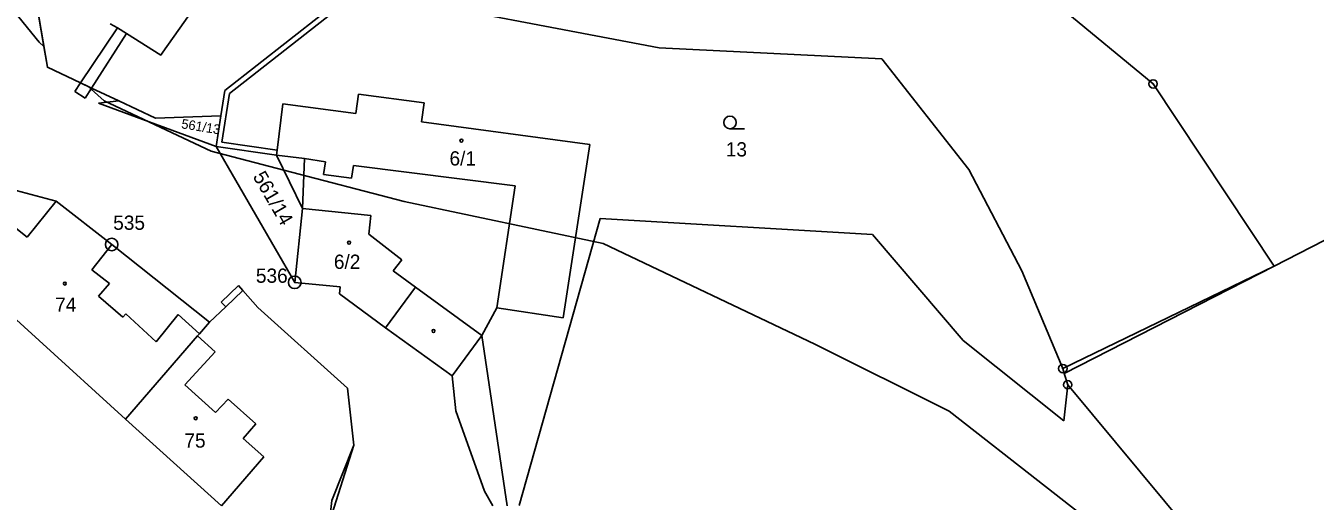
# Model space of a CAD drawing. Extents: x -725765 to -723182, y -1052705 to -1049154.
# Drawn here: x -724740.7 to -724587, y -1050771.8 to -1050715 of the extents above; entities that cross this region are included whole.
import ezdxf

# ---------------------------------------------------------------- set-up
doc = ezdxf.new("R2010")
doc.units = 0
for name, color, linetype in [('Vrstva 1', 7, 'Continuous'), ('Vrstva 17', 7, 'Continuous'), ('Vrstva 18', 7, 'Continuous'), ('Vrstva 19', 7, 'Continuous'), ('Vrstva 25', 7, 'Continuous'), ('Vrstva 4', 7, 'Continuous'), ('Vrstva 52', 7, 'Continuous')]:
    doc.layers.add(name, color=color, linetype=linetype)

msp = doc.modelspace()

# ---------------------------------------------------------------- linework, layer by layer
at = {"layer": 'Vrstva 1'}
for points in [[(-724741.74, -1050698.99), (-724738.17, -1050719.97)], [(-724724.39, -1050718.17), (-724717.58, -1050708.46)], [(-724716.99, -1050722.76), (-724701.57, -1050710.63)], [(-724700.87, -1050710.84), (-724665.21, -1050717.66)], [(-724617.37, -1050712.82), (-724606.3, -1050721.96)], [(-724730.67, -1050714.79), (-724729.82, -1050715.26)], [(-724729.82, -1050715.26), (-724728.73, -1050715.96)], [(-724728.73, -1050715.96), (-724724.64, -1050718.52)], [(-724665.21, -1050717.66), (-724638.64, -1050718.98)], [(-724724.64, -1050718.52), (-724724.39, -1050718.17)], [(-724638.64, -1050718.98), (-724628.28, -1050732.18)], [(-724738.17, -1050719.97), (-724734.22, -1050721.83)], [(-724734.22, -1050721.83), (-724732.9, -1050722.45)], [(-724732.9, -1050722.45), (-724729.65, -1050723.98)], [(-724606.3, -1050721.96), (-724591.87, -1050743.69)], [(-724732.06, -1050724.25), (-724729.65, -1050723.98)], [(-724732.06, -1050724.25), (-724718.05, -1050729.41)], [(-724729.65, -1050723.98), (-724725.26, -1050726.05)], [(-724717.47, -1050725.76), (-724716.99, -1050722.76)], [(-724701.4, -1050725.49), (-724701.07, -1050723.18)], [(-724701.07, -1050723.18), (-724693.23, -1050724.2)], [(-724693.53, -1050726.5), (-724693.23, -1050724.2)], [(-724725.26, -1050726.05), (-724717.47, -1050725.76)], [(-724718.05, -1050729.41), (-724717.47, -1050725.76)], [(-724710.77, -1050729.85), (-724710.07, -1050724.33)], [(-724710.07, -1050724.33), (-724701.4, -1050725.49)], [(-724693.53, -1050726.5), (-724673.48, -1050729.18)], [(-724718.05, -1050729.41), (-724708.67, -1050745.64)], [(-724718.05, -1050729.41), (-724710.85, -1050730.45)], [(-724710.85, -1050730.45), (-724710.77, -1050729.85)], [(-724676.64, -1050749.89), (-724673.48, -1050729.18)], [(-724591.87, -1050743.69), (-724565.12, -1050730)], [(-724710.85, -1050730.45), (-724707.75, -1050736.81)], [(-724747.3, -1050733.24), (-724737.14, -1050735.96)], [(-724628.28, -1050732.18), (-724621.93, -1050744.27)], [(-724737.14, -1050735.96), (-724730.5, -1050741.12)], [(-724708.67, -1050745.64), (-724707.75, -1050736.81)], [(-724707.75, -1050736.81), (-724699.6, -1050737.65)], [(-724699.84, -1050739.89), (-724699.6, -1050737.65)], [(-724681.91, -1050772.28), (-724672.23, -1050738.03)], [(-724672.23, -1050738.03), (-724639.76, -1050739.93)], [(-724730.5, -1050741.12), (-724718.82, -1050750.37)], [(-724699.84, -1050739.89), (-724695.9, -1050742.96)], [(-724639.76, -1050739.93), (-724628.95, -1050752.57)], [(-724749.48, -1050743.18), (-724728.86, -1050761.96)], [(-724696.91, -1050744.25), (-724695.9, -1050742.96)], [(-724696.91, -1050744.25), (-724694.25, -1050746.21)], [(-724621.93, -1050744.27), (-724617.06, -1050755.93)], [(-724617.06, -1050755.93), (-724591.87, -1050743.69)], [(-724708.67, -1050745.64), (-724703.25, -1050746.18)], [(-724716.88, -1050748.54), (-724714.85, -1050746.62)], [(-724714.85, -1050746.62), (-724713.07, -1050748.63)], [(-724703.33, -1050747.02), (-724703.25, -1050746.18)], [(-724703.33, -1050747.02), (-724697.83, -1050751.07)], [(-724697.83, -1050751.07), (-724694.25, -1050746.21)], [(-724718.82, -1050750.37), (-724716.88, -1050748.54)], [(-724713.07, -1050748.63), (-724702.37, -1050758.27)], [(-724686.37, -1050751.98), (-724684.58, -1050748.68)], [(-724684.58, -1050748.68), (-724676.64, -1050749.89)], [(-724720.03, -1050751.77), (-724718.82, -1050750.37)], [(-724720.26, -1050752.02), (-724720.03, -1050751.77)], [(-724697.83, -1050751.07), (-724689.9, -1050756.78)], [(-724728.86, -1050761.96), (-724720.26, -1050752.02)], [(-724689.9, -1050756.78), (-724686.37, -1050751.98)], [(-724686.37, -1050751.98), (-724683.34, -1050772.29)], [(-724628.95, -1050752.57), (-724616.96, -1050762.18)], [(-724617.06, -1050755.93), (-724616.89, -1050756.5)], [(-724616.89, -1050756.5), (-724616.48, -1050757.85)], [(-724616.96, -1050762.18), (-724616.48, -1050757.85)], [(-724616.48, -1050757.85), (-724599.21, -1050778.62)], [(-724702.37, -1050758.27), (-724701.62, -1050765.05)], [(-724728.86, -1050761.96), (-724717.41, -1050772.31)], [(-724704.54, -1050774.22), (-724701.62, -1050765.05)]]:
    msp.add_lwpolyline(points, dxfattribs=at)
at = {"layer": 'Vrstva 25'}
msp.add_lwpolyline([(-724656.76, -1050727.31), (-724655.01, -1050727.31)], dxfattribs=at)
for centre, radius in [((-724606.3, -1050721.96), 0.5), ((-724606.3, -1050721.96), 0.032), ((-724656.76, -1050726.56), 0.75), ((-724688.79, -1050728.73), 0.175), ((-724730.5, -1050741.12), 0.75), ((-724730.5, -1050741.12), 0.032), ((-724702.19, -1050740.9), 0.175), ((-724736.09, -1050745.78), 0.175), ((-724708.67, -1050745.64), 0.75), ((-724708.67, -1050745.64), 0.032), ((-724692.12, -1050751.44), 0.175), ((-724617.06, -1050755.93), 0.5), ((-724617.06, -1050755.93), 0.032), ((-724616.48, -1050757.85), 0.5), ((-724616.48, -1050757.85), 0.032), ((-724720.48, -1050761.85), 0.175)]:
    msp.add_circle(centre, radius, dxfattribs=at)
at = {"layer": 'Vrstva 4'}
for points in [[(-724716.44, -1050723.09), (-724700.87, -1050710.84)], [(-724734.22, -1050721.83), (-724729.82, -1050715.26)], [(-724732.9, -1050722.45), (-724728.73, -1050715.96)], [(-724734.91, -1050722.86), (-724734.22, -1050721.83)], [(-724733.68, -1050723.67), (-724732.9, -1050722.45)], [(-724734.91, -1050722.86), (-724733.68, -1050723.67)], [(-724717.36, -1050728.9), (-724716.44, -1050723.09)], [(-724717.36, -1050728.9), (-724710.77, -1050729.85)], [(-724710.85, -1050730.45), (-724707.51, -1050730.88)], [(-724707.75, -1050736.81), (-724707.51, -1050730.88)], [(-724707.51, -1050730.88), (-724705.01, -1050731.24)], [(-724705.22, -1050732.77), (-724705.01, -1050731.24)], [(-724701.9, -1050733.2), (-724701.67, -1050731.69)], [(-724701.67, -1050731.69), (-724682.39, -1050734.13)], [(-724705.22, -1050732.77), (-724701.9, -1050733.2)], [(-724684.58, -1050748.68), (-724682.39, -1050734.13)], [(-724740.6, -1050740.24), (-724737.14, -1050735.96)], [(-724741.92, -1050739.17), (-724740.6, -1050740.24)], [(-724732.86, -1050744.14), (-724730.5, -1050741.12)], [(-724732.86, -1050744.14), (-724730.78, -1050745.77)], [(-724616.89, -1050756.5), (-724591.87, -1050743.69)], [(-724732.06, -1050747.29), (-724730.78, -1050745.77)], [(-724732.06, -1050747.29), (-724729.19, -1050749.78)], [(-724717.44, -1050747.99), (-724715.39, -1050746)], [(-724715.39, -1050746), (-724714.85, -1050746.62)], [(-724694.25, -1050746.21), (-724686.37, -1050751.98)], [(-724717.44, -1050747.99), (-724716.88, -1050748.54)], [(-724729.19, -1050749.78), (-724728.82, -1050749.4)], [(-724728.82, -1050749.4), (-724725.2, -1050752.72)], [(-724725.2, -1050752.72), (-724722.59, -1050749.49)], [(-724722.59, -1050749.49), (-724720.03, -1050751.77)], [(-724720.26, -1050752.02), (-724718.16, -1050753.92)], [(-724721.76, -1050757.88), (-724718.16, -1050753.92)], [(-724721.76, -1050757.88), (-724718.12, -1050761.18)], [(-724689.9, -1050756.78), (-724689.47, -1050760.95)], [(-724718.12, -1050761.18), (-724716.59, -1050759.59)], [(-724716.59, -1050759.59), (-724713.31, -1050762.52)], [(-724689.47, -1050760.95), (-724686.05, -1050770.54)], [(-724714.81, -1050764.26), (-724713.31, -1050762.52)], [(-724714.81, -1050764.26), (-724712.35, -1050766.47)], [(-724704.24, -1050771.67), (-724701.62, -1050765.05)], [(-724717.41, -1050772.31), (-724712.35, -1050766.47)], [(-724704.54, -1050774.22), (-724704.24, -1050771.67)], [(-724686.05, -1050770.54), (-724685.05, -1050772.29)]]:
    msp.add_lwpolyline(points, dxfattribs=at)
at = {"layer": 'Vrstva 52'}
for points in [[(-724797.81, -1050648.79), (-724791.63, -1050653), (-724781.31, -1050664), (-724773.97, -1050672.98), (-724764.13, -1050685), (-724751.31, -1050702), (-724746.1, -1050708.41), (-724739.13, -1050717), (-724738.59, -1050717.48)], [(-724733.3, -1050722.26), (-724732.9, -1050722.45), (-724729.65, -1050723.98), (-724725.26, -1050726.05), (-724717.47, -1050725.76), (-724716.99, -1050722.76), (-724701.57, -1050710.63), (-724699.64, -1050709.04), (-724673.73, -1050676.36), (-724671.44, -1050673.47), (-724670.16, -1050671.86), (-724650.15, -1050674.46), (-724638.72, -1050676.24)], [(-724738.59, -1050717.48), (-724741.74, -1050698.99)], [(-724730.67, -1050714.79), (-724729.82, -1050715.26), (-724728.73, -1050715.96), (-724724.64, -1050718.52), (-724724.39, -1050718.17), (-724717.58, -1050708.46)], [(-724738.59, -1050717.48), (-724738.17, -1050719.97), (-724734.22, -1050721.83), (-724733.3, -1050722.26)], [(-724733.3, -1050722.26), (-724731.38, -1050724), (-724718.63, -1050730), (-724709.97, -1050732.26), (-724695.63, -1050736), (-724671.88, -1050741), (-724646.63, -1050753), (-724630.63, -1050761), (-724607.63, -1050779), (-724593.38, -1050794), (-724585.13, -1050806), (-724577.38, -1050827), (-724569.81, -1050845), (-724556, -1050870), (-724545.81, -1050894), (-724531.69, -1050917), (-724517.63, -1050935), (-724505.66, -1050947.46)]]:
    msp.add_lwpolyline(points, dxfattribs=at)

# ---------------------------------------------------------------- texts
at = {"layer": 'Vrstva 17'}
for s, p in [('535', (-724730.32, -1050739.37)), ('536', (-724713.3, -1050745.69))]:
    msp.add_text(s, height=1.7, dxfattribs=at).set_placement(p)
at = {"layer": 'Vrstva 18'}
for s, height, rotation, p in [('561/13', 1.14, 350.9028, (-724722.25, -1050727.25)), ('561/14', 1.7, 300.1024, (-724713.72, -1050733))]:
    msp.add_text(s, height=height, rotation=rotation, dxfattribs=at).set_placement(p)
msp.add_text('13', height=1.7, dxfattribs=at).set_placement((-724657.26, -1050730.62))
at = {"layer": 'Vrstva 19'}
for s, p in [('6/1', (-724690.21, -1050731.7)), ('6/2', (-724704, -1050744.03)), ('74', (-724737.24, -1050749.15)), ('75', (-724721.83, -1050765.36))]:
    msp.add_text(s, height=1.7, dxfattribs=at).set_placement(p)

doc.saveas('drawing.dxf')
